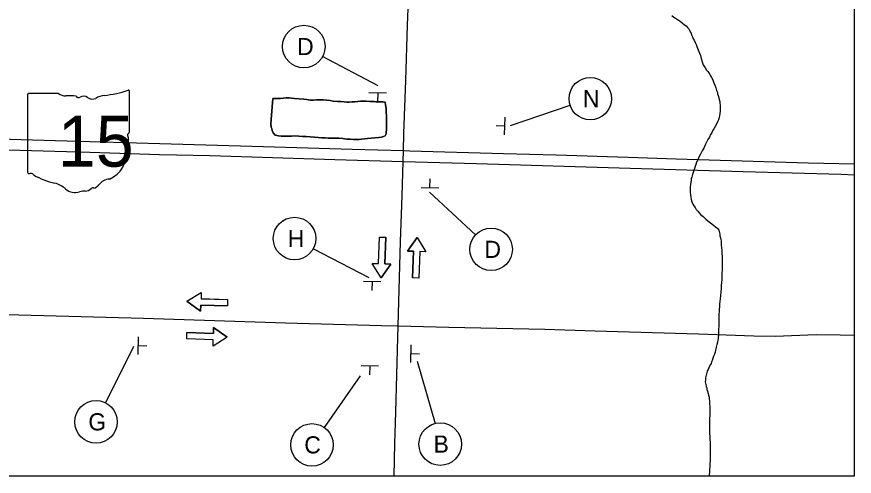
# Model space of a CAD drawing. Extents: x 1633.3 to 1707.6, y 1081.5 to 1106.
# Drawn here: x 1640.38 to 1648.01, y 1086.42 to 1090.6 of the extents above; entities that cross this region are included whole.
import ezdxf

# ---------------------------------------------------------------- set-up
doc = ezdxf.new("R2010")
doc.units = 0
for name, color, linetype in [('GM_X_County_Road', 7, 'Continuous'), ('GM_X_Minor_Lake', 7, 'Continuous'), ('GM_X_Minor_River', 7, 'Continuous'), ('GM_X_State_Route', 7, 'Continuous'), ('GM_X_State_Shield', 7, 'Continuous'), ('SH_Data', 7, 'Continuous'), ('SH_Text', 7, 'Continuous'), ('SN_P_Signs', 7, 'Continuous')]:
    doc.layers.add(name, color=color, linetype=linetype)

msp = doc.modelspace()

# ---------------------------------------------------------------- linework, layer by layer
at = {"layer": 'GM_X_County_Road'}
for points in [[(1643.9071, 1089.384), (1643.9114, 1089.5404), (1643.9273, 1090.0213), (1643.9445, 1090.5242), (1643.9565, 1090.8293), (1643.9741, 1091.2019), (1643.9856, 1091.5297), (1644.0086, 1092.1887), (1644.0208, 1092.5134), (1644.0277, 1092.6341), (1644.0323, 1092.6918), (1644.0369, 1092.7305), (1644.045, 1092.7687), (1644.0543, 1092.7889), (1644.0682, 1092.8156), (1644.0814, 1092.8346), (1644.102, 1092.8585)], [(1643.9044, 1089.2854), (1643.9071, 1089.384)], [(1643.8593, 1087.7897), (1643.881, 1088.5565), (1643.8957, 1088.9718), (1643.9044, 1089.2854)], [(1636.7029, 1087.9843), (1636.7291, 1087.9834), (1637.1782, 1087.9683), (1637.6688, 1087.9589), (1639.2, 1087.9178), (1640.4033, 1087.8897), (1641.5407, 1087.8579), (1642.8312, 1087.8177), (1643.7062, 1087.7937), (1643.8593, 1087.7897)], [(1643.8209, 1086.4207), (1643.8292, 1086.7195), (1643.8384, 1087.0037), (1643.8561, 1087.6817), (1643.8593, 1087.7897)], [(1643.8593, 1087.7897), (1644.3187, 1087.7778), (1645.1936, 1087.7586), (1645.6529, 1087.7435), (1646.5935, 1087.718), (1647.0963, 1087.6977), (1647.2932, 1087.6953), (1647.665, 1087.7091), (1647.8837, 1087.7067), (1648.0121, 1087.703)]]:
    msp.add_lwpolyline(points, dxfattribs=at)
at = {"layer": 'GM_X_Minor_Lake'}
for points in [[(1642.7169, 1089.8567), (1642.7222, 1089.8567), (1642.7329, 1089.8566), (1642.7463, 1089.8593), (1642.765, 1089.8565), (1642.7864, 1089.8591), (1642.8132, 1089.8617), (1642.84, 1089.8643), (1642.8667, 1089.8642), (1642.8881, 1089.8615), (1642.9149, 1089.8587), (1643.0005, 1089.8504), (1643.0272, 1089.8477), (1643.0567, 1089.8422), (1643.0861, 1089.8421), (1643.1155, 1089.8447), (1643.1476, 1089.8446), (1643.1771, 1089.8445), (1643.2065, 1089.8417), (1643.2386, 1089.839), (1643.268, 1089.8335), (1643.3082, 1089.8307), (1643.3376, 1089.8306), (1643.367, 1089.8279), (1643.3911, 1089.8251), (1643.4125, 1089.825), (1643.4393, 1089.8276), (1643.4634, 1089.8275), (1643.4901, 1089.8301), (1643.5142, 1089.8327), (1643.5383, 1089.8327), (1643.5677, 1089.8326), (1643.5998, 1089.8298), (1643.6212, 1089.8297), (1643.64, 1089.8297), (1643.656, 1089.8269), (1643.672, 1089.8269), (1643.6908, 1089.8268), (1643.7095, 1089.8268), (1643.7229, 1089.8267), (1643.7389, 1089.824), (1643.7442, 1089.7999), (1643.7469, 1089.7865), (1643.7495, 1089.7705), (1643.7495, 1089.749), (1643.7494, 1089.7276), (1643.752, 1089.7035), (1643.752, 1089.6875), (1643.752, 1089.6688), (1643.7519, 1089.6527), (1643.7519, 1089.634), (1643.7518, 1089.6179), (1643.7518, 1089.5725), (1643.749, 1089.5511), (1643.749, 1089.5377), (1643.7409, 1089.519), (1643.7248, 1089.511), (1643.7061, 1089.5057), (1643.682, 1089.5031), (1643.6419, 1089.5006), (1643.6124, 1089.498), (1643.5803, 1089.4927), (1643.5509, 1089.4902), (1643.5241, 1089.4876), (1643.5027, 1089.485), (1643.4786, 1089.485), (1643.4519, 1089.4851), (1643.4224, 1089.4879), (1643.3903, 1089.488), (1643.3556, 1089.4935), (1643.3208, 1089.4962), (1643.278, 1089.4964), (1643.2485, 1089.4965), (1643.2218, 1089.4966), (1643.1923, 1089.4993), (1643.1629, 1089.4994), (1643.1308, 1089.5022), (1643.096, 1089.505), (1643.0586, 1089.5078), (1643.0211, 1089.5133), (1642.9863, 1089.5134), (1642.9542, 1089.5161), (1642.9168, 1089.5189), (1642.8874, 1089.5164), (1642.8606, 1089.5138), (1642.8418, 1089.5138), (1642.8231, 1089.5139), (1642.8071, 1089.5139), (1642.7937, 1089.514), (1642.7696, 1089.5167), (1642.7375, 1089.5249), (1642.7188, 1089.5463), (1642.7109, 1089.5677), (1642.7082, 1089.5838), (1642.7029, 1089.5972), (1642.7003, 1089.624), (1642.7004, 1089.6668), (1642.7169, 1089.8567)], [(1642.7169, 1089.8567), (1642.7004, 1089.6668), (1642.7003, 1089.624), (1642.7029, 1089.5972), (1642.7082, 1089.5838), (1642.7109, 1089.5677), (1642.7188, 1089.5463), (1642.7375, 1089.5249), (1642.7696, 1089.5167), (1642.7937, 1089.514), (1642.8071, 1089.5139), (1642.8231, 1089.5139), (1642.8418, 1089.5138), (1642.8606, 1089.5138), (1642.8874, 1089.5164), (1642.9168, 1089.5189), (1642.9542, 1089.5161), (1642.9863, 1089.5134), (1643.0211, 1089.5133), (1643.0586, 1089.5078), (1643.096, 1089.505), (1643.1308, 1089.5022), (1643.1629, 1089.4994), (1643.1923, 1089.4993), (1643.2218, 1089.4966), (1643.2485, 1089.4965), (1643.278, 1089.4964), (1643.3208, 1089.4962), (1643.3556, 1089.4935), (1643.3903, 1089.488), (1643.4224, 1089.4879), (1643.4519, 1089.4851), (1643.4786, 1089.485), (1643.5027, 1089.485), (1643.5241, 1089.4876), (1643.5509, 1089.4902), (1643.5803, 1089.4927), (1643.6124, 1089.498), (1643.6419, 1089.5006), (1643.682, 1089.5031), (1643.7061, 1089.5057), (1643.7248, 1089.511), (1643.7409, 1089.519), (1643.749, 1089.5377), (1643.749, 1089.5511), (1643.7518, 1089.5725), (1643.7518, 1089.6179), (1643.7519, 1089.634), (1643.7519, 1089.6527), (1643.752, 1089.6688)], [(1643.752, 1089.6688), (1643.752, 1089.6875), (1643.752, 1089.7035), (1643.7494, 1089.7276), (1643.7495, 1089.749), (1643.7495, 1089.7705), (1643.7469, 1089.7865), (1643.7442, 1089.7999), (1643.7389, 1089.824), (1643.7229, 1089.8267), (1643.7095, 1089.8268), (1643.6908, 1089.8268), (1643.672, 1089.8269), (1643.656, 1089.8269), (1643.64, 1089.8297), (1643.6212, 1089.8297), (1643.5998, 1089.8298), (1643.5677, 1089.8326), (1643.5383, 1089.8327), (1643.5142, 1089.8327), (1643.4901, 1089.8301), (1643.4634, 1089.8275), (1643.4393, 1089.8276), (1643.4125, 1089.825), (1643.3911, 1089.8251), (1643.367, 1089.8279), (1643.3376, 1089.8306), (1643.3082, 1089.8307), (1643.268, 1089.8335), (1643.2386, 1089.839), (1643.2065, 1089.8417), (1643.1771, 1089.8445), (1643.1476, 1089.8446), (1643.1155, 1089.8447), (1643.0861, 1089.8421), (1643.0567, 1089.8422), (1643.0272, 1089.8477), (1643.0005, 1089.8504), (1642.9149, 1089.8587), (1642.8881, 1089.8615), (1642.8667, 1089.8642), (1642.84, 1089.8643), (1642.8132, 1089.8617), (1642.7864, 1089.8591), (1642.765, 1089.8565), (1642.7463, 1089.8593), (1642.7329, 1089.8566), (1642.7222, 1089.8567), (1642.7169, 1089.8567)]]:
    msp.add_lwpolyline(points, dxfattribs=at)
at = {"layer": 'GM_X_Minor_River'}
for points in [[(1646.3496, 1090.6129), (1646.3683, 1090.5995), (1646.3844, 1090.5887), (1646.4031, 1090.578), (1646.4271, 1090.5619), (1646.4458, 1090.5457), (1646.4672, 1090.5296), (1646.4805, 1090.5189), (1646.4939, 1090.5054), (1646.5046, 1090.492), (1646.5126, 1090.4786), (1646.5179, 1090.4652), (1646.5259, 1090.4518), (1646.5312, 1090.4384), (1646.5392, 1090.4197)], [(1646.5392, 1090.4197), (1646.5445, 1090.4009), (1646.5552, 1090.3875), (1646.5631, 1090.3688), (1646.5711, 1090.35), (1646.5791, 1090.3313), (1646.603, 1090.2697), (1646.611, 1090.2482), (1646.619, 1090.2214), (1646.627, 1090.192), (1646.6376, 1090.1652), (1646.6536, 1090.1357), (1646.6669, 1090.1169), (1646.6776, 1090.1035), (1646.6883, 1090.0901), (1646.6963, 1090.0767), (1646.7043, 1090.0633), (1646.7123, 1090.0499), (1646.7229, 1090.0285), (1646.7309, 1090.007), (1646.7415, 1089.9803), (1646.7522, 1089.9561), (1646.7575, 1089.9321), (1646.7654, 1089.9133), (1646.7681, 1089.8999), (1646.7734, 1089.8838), (1646.7787, 1089.8651), (1646.7814, 1089.849), (1646.7867, 1089.8303), (1646.7893, 1089.8142), (1646.7919, 1089.7982), (1646.7919, 1089.7821), (1646.7919, 1089.7607), (1646.7918, 1089.7447), (1646.7891, 1089.7179), (1646.7864, 1089.7045), (1646.781, 1089.6858), (1646.7756, 1089.6644), (1646.7675, 1089.6457), (1646.7568, 1089.6244), (1646.746, 1089.603), (1646.7326, 1089.5816), (1646.7218, 1089.5629), (1646.7138, 1089.5443), (1646.703, 1089.5309), (1646.695, 1089.5069), (1646.6788, 1089.4855), (1646.6681, 1089.4668), (1646.6573, 1089.4427), (1646.6439, 1089.4107), (1646.6278, 1089.3813), (1646.6116, 1089.3519), (1646.5982, 1089.3252), (1646.5874, 1089.3012), (1646.5767, 1089.2798), (1646.5686, 1089.2584), (1646.5444, 1089.1836), (1646.539, 1089.1649), (1646.5336, 1089.1435), (1646.5282, 1089.1275), (1646.5255, 1089.1114), (1646.5228, 1089.0954), (1646.52, 1089.074), (1646.5173, 1089.0499), (1646.5172, 1089.0285), (1646.5172, 1089.0044), (1646.5198, 1088.9803), (1646.5224, 1088.9563), (1646.5277, 1088.9375), (1646.533, 1088.9188), (1646.541, 1088.8973), (1646.5517, 1088.8812), (1646.5624, 1088.8652), (1646.573, 1088.8491), (1646.5864, 1088.833), (1646.5997, 1088.8169), (1646.6157, 1088.8008), (1646.6371, 1088.7847), (1646.6611, 1088.7605), (1646.6798, 1088.7444), (1646.7038, 1088.7256), (1646.7306, 1088.7041), (1646.7519, 1088.688), (1646.7653, 1088.6772), (1646.7786, 1088.6585), (1646.7839, 1088.637), (1646.7866, 1088.6237), (1646.7892, 1088.6076), (1646.7945, 1088.5888), (1646.7972, 1088.5755), (1646.7998, 1088.5621), (1646.7998, 1088.5433), (1646.7997, 1088.5246), (1646.8023, 1088.5005), (1646.805, 1088.4738), (1646.8076, 1088.4497), (1646.8102, 1088.4176), (1646.8101, 1088.3962), (1646.8101, 1088.3694), (1646.81, 1088.3453), (1646.8099, 1088.3159)], [(1646.8099, 1088.3159), (1646.8071, 1088.249), (1646.8071, 1088.2303), (1646.807, 1088.2089), (1646.8043, 1088.1848), (1646.8015, 1088.1554), (1646.7988, 1088.1286), (1646.796, 1088.0965), (1646.7933, 1088.0645), (1646.7906, 1088.035), (1646.7878, 1088.011), (1646.7851, 1087.9869), (1646.785, 1087.9628), (1646.7823, 1087.9414), (1646.7823, 1087.9173), (1646.7795, 1087.8986), (1646.7795, 1087.8745), (1646.7794, 1087.8398), (1646.7793, 1087.8103), (1646.7793, 1087.7836), (1646.7766, 1087.7595), (1646.7765, 1087.7381), (1646.7765, 1087.7167), (1646.7764, 1087.7006), (1646.7737, 1087.6873), (1646.7737, 1087.6739), (1646.7683, 1087.6579), (1646.7656, 1087.6418), (1646.7602, 1087.6204), (1646.7548, 1087.5964), (1646.7521, 1087.5803), (1646.7494, 1087.567), (1646.744, 1087.5482), (1646.7386, 1087.5322), (1646.7332, 1087.5189), (1646.7278, 1087.5055), (1646.7197, 1087.4841), (1646.7116, 1087.4601), (1646.7089, 1087.4467), (1646.6982, 1087.428), (1646.6874, 1087.4066), (1646.6821, 1087.3933), (1646.674, 1087.3772), (1646.6578, 1087.3158), (1646.6578, 1087.297), (1646.655, 1087.2783), (1646.6603, 1087.2542), (1646.663, 1087.2381), (1646.6683, 1087.2248), (1646.6709, 1087.2087), (1646.6763, 1087.1953), (1646.6816, 1087.1739), (1646.6842, 1087.1578), (1646.6895, 1087.1417), (1646.6922, 1087.1284), (1646.6948, 1087.1043), (1646.6947, 1087.0909), (1646.6947, 1087.0775), (1646.6973, 1087.0588), (1646.6973, 1087.0347), (1646.6972, 1086.9812), (1646.6944, 1086.9384), (1646.6943, 1086.9036), (1646.6942, 1086.8688), (1646.6942, 1086.8367), (1646.6941, 1086.81), (1646.6967, 1086.7832), (1646.6966, 1086.7538), (1646.6992, 1086.727), (1646.6992, 1086.6922), (1646.6991, 1086.6655), (1646.699, 1086.6307), (1646.699, 1086.5986), (1646.6989, 1086.5638), (1646.6961, 1086.5344), (1646.6961, 1086.5103), (1646.6934, 1086.4863), (1646.6933, 1086.4595), (1646.6906, 1086.4327), (1646.6894, 1086.4207)]]:
    msp.add_lwpolyline(points, dxfattribs=at)
at = {"layer": 'GM_X_State_Route'}
for points in [[(1633.3121, 1089.6917), (1633.8444, 1089.6764), (1634.5421, 1089.656), (1635.0244, 1089.6397), (1635.5067, 1089.6277), (1636.4013, 1089.603), (1636.7895, 1089.5915), (1637.6692, 1089.5652), (1639.746, 1089.5046), (1640.4237, 1089.486), (1640.9483, 1089.4695), (1641.5823, 1089.4514), (1642.6316, 1089.4208), (1643.4405, 1089.3971), (1643.9071, 1089.384), (1643.9651, 1089.3826), (1644.8177, 1089.3571), (1645.2987, 1089.3441), (1645.9544, 1089.3239), (1646.3915, 1089.3102), (1647.5918, 1089.2715), (1647.7355, 1089.2693), (1648.0121, 1089.264)], [(1633.3121, 1089.5922), (1634.2415, 1089.565), (1635.2906, 1089.5338), (1635.99, 1089.5137), (1636.7846, 1089.489), (1637.3802, 1089.4708), (1637.8182, 1089.4595), (1638.6457, 1089.4389), (1639.4549, 1089.4149), (1641.0515, 1089.3682), (1641.6858, 1089.3496), (1642.145, 1089.338), (1643.2823, 1089.3034), (1643.9044, 1089.2854), (1644.5726, 1089.2656), (1645.9723, 1089.2243), (1647.0002, 1089.1934), (1647.8935, 1089.1689), (1648.0121, 1089.1646)]]:
    msp.add_lwpolyline(points, dxfattribs=at)
at = {"layer": 'GM_X_State_Shield'}
for p, q in [((1641.4116, 1089.5533), (1641.4116, 1089.9218)), ((1640.4835, 1089.8923), (1640.4835, 1089.1878)), ((1640.7644, 1089.9044), (1640.4926, 1089.9044)), ((1641.4115, 1089.5534), (1641.4116, 1089.5533))]:
    msp.add_line(p, q, dxfattribs=at)
for centre, radius, start, end in [((1641.081, 1090.8647), 0.9842, 275.84447, 288.90645), ((1641.4013, 1089.9234), 0.0103, 351.86209, 97.738), ((1640.4941, 1089.8938), 0.0108, 98.1301, 188.1301), ((1640.8292, 1089.9861), 0.1043, 231.61951, 271.11188), ((1640.8638, 1089.5089), 0.3744, 80.48669, 94.98827), ((1640.9487, 1089.8974), 0.0301, 219.79206, 297.10237), ((1640.9929, 1089.816), 0.0626, 54.46668, 119.14113), ((1641.0737, 1089.9277), 0.0753, 233.85621, 294.82819), ((1641.2066, 1089.6892), 0.198, 97.34618, 120.76885), ((1641.4092, 1089.5263), 0.016, 107.94398, 210.33697), ((1641.4006, 1089.5519), 0.0111, 289.60381, 7.73413), ((1641.3075, 1089.4797), 0.096, 340.03296, 23.64957), ((1641.1361, 1089.3523), 0.2462, 292.30889, 8.98584), ((1641.4486, 1089.3991), 0.0698, 136.8065, 186.92959), ((1640.4942, 1089.1863), 0.0108, 171.95839, 258.30661), ((1640.4959, 1089.2584), 0.0828, 267.33899, 280.60386), ((1640.5128, 1089.1472), 0.0298, 29.74838, 93.27175), ((1640.8897, 1089.7801), 0.7108, 240.41292, 257.1985), ((1640.6778, 1088.8714), 0.2224, 47.18416, 75.83597), ((1641.2399, 1088.9901), 0.1348, 94.40312, 142.57675), ((1640.9183, 1089.1437), 0.1411, 230.70037, 286.29184), ((1640.9998, 1088.9001), 0.116, 85.69512, 111.20995), ((1641.0101, 1089.0909), 0.0752, 268.77702, 315.54927), ((1641.0781, 1089.0227), 0.0212, 65.75173, 132.64842), ((1641.0691, 1089.1196), 0.0795, 282.87319, 323.27711)]:
    msp.add_arc(centre, radius, start, end, dxfattribs=at)
at = {"layer": 'SH_Data'}
msp.add_lwpolyline([(1633.3121, 1106.0207), (1648.0121, 1106.0207), (1648.0121, 1086.4207), (1633.3121, 1086.4207)], close=True, dxfattribs=at)
at = {"layer": 'SH_Text'}
for p, q in [((1643.6771, 1089.9731), (1643.1697, 1090.2389)), ((1644.8814, 1089.6128), (1645.4241, 1089.7963)), ((1644.1428, 1089.0064), (1644.5641, 1088.6182)), ((1643.6801, 1088.3555), (1643.6886, 1088.5974)), ((1643.6886, 1088.5974), (1643.7465, 1088.5954)), ((1643.7381, 1088.3535), (1643.7465, 1088.5954)), ((1644.0316, 1088.594), (1643.9424, 1088.4696)), ((1644.0316, 1088.594), (1644.1119, 1088.4637)), ((1643.5931, 1088.2255), (1643.0857, 1088.4913)), ((1643.9424, 1088.4696), (1643.997, 1088.4677)), ((1643.997, 1088.4677), (1643.9886, 1088.2258)), ((1644.055, 1088.4656), (1644.0465, 1088.2238)), ((1644.1119, 1088.4637), (1644.055, 1088.4656)), ((1643.7035, 1088.2271), (1643.6232, 1088.3575)), ((1643.6232, 1088.3575), (1643.6801, 1088.3555)), ((1643.7035, 1088.2271), (1643.7927, 1088.3516)), ((1643.7927, 1088.3516), (1643.7381, 1088.3535)), ((1644.0465, 1088.2238), (1643.9886, 1088.2258)), ((1641.9352, 1088.0129), (1642.0655, 1088.0934)), ((1642.0655, 1088.0934), (1642.0636, 1088.0365)), ((1641.9352, 1088.0129), (1642.0598, 1087.9239)), ((1642.0636, 1088.0365), (1642.3055, 1088.0284)), ((1642.3055, 1088.0284), (1642.3035, 1087.9704)), ((1642.0598, 1087.9239), (1642.0616, 1087.9785)), ((1642.0616, 1087.9785), (1642.3035, 1087.9704)), ((1641.9324, 1087.6699), (1641.9343, 1087.7278)), ((1642.1762, 1087.7198), (1641.9343, 1087.7278)), ((1642.178, 1087.7743), (1642.1762, 1087.7198)), ((1642.3026, 1087.6854), (1642.178, 1087.7743)), ((1642.1743, 1087.6618), (1641.9324, 1087.6699)), ((1642.3026, 1087.6854), (1642.1724, 1087.6048)), ((1642.1724, 1087.6048), (1642.1743, 1087.6618)), ((1641.4476, 1087.6024), (1641.1944, 1087.0885)), ((1644.0309, 1087.4684), (1644.194, 1086.9008)), ((1643.5128, 1087.3343), (1643.1859, 1086.8639))]:
    msp.add_line(p, q, dxfattribs=at)
for points in [[(1643.9071, 1089.384), (1643.9114, 1089.5404), (1643.9273, 1090.0213), (1643.9445, 1090.5242), (1643.9565, 1090.8293), (1643.9741, 1091.2019), (1643.9856, 1091.5297), (1644.0086, 1092.1887), (1644.0208, 1092.5134), (1644.0277, 1092.6341), (1644.0323, 1092.6918), (1644.0369, 1092.7305), (1644.045, 1092.7687), (1644.0543, 1092.7889), (1644.0682, 1092.8156), (1644.0814, 1092.8346), (1644.102, 1092.8585)], [(1643.8593, 1087.7897), (1643.881, 1088.5565), (1643.8957, 1088.9718), (1643.9071, 1089.384)], [(1636.7029, 1087.9843), (1636.7291, 1087.9834), (1637.1782, 1087.9683), (1637.6688, 1087.9589), (1639.2, 1087.9178), (1640.4033, 1087.8897), (1641.5407, 1087.8579), (1642.8312, 1087.8177), (1643.7062, 1087.7937), (1643.8593, 1087.7897)]]:
    msp.add_lwpolyline(points, dxfattribs=at)
for points in [[(1643.7465, 1088.5954), (1643.7381, 1088.3535), (1643.7927, 1088.3516), (1643.7035, 1088.2271), (1643.6232, 1088.3575), (1643.6802, 1088.3555), (1643.6886, 1088.5974)], [(1643.9886, 1088.2258), (1643.997, 1088.4677), (1643.9424, 1088.4696), (1644.0316, 1088.594), (1644.1119, 1088.4637), (1644.055, 1088.4656), (1644.0465, 1088.2238)], [(1642.3035, 1087.9704), (1642.0616, 1087.9785), (1642.0598, 1087.9239), (1641.9352, 1088.0129), (1642.0654, 1088.0934), (1642.0636, 1088.0364), (1642.3055, 1088.0284)], [(1641.9343, 1087.7278), (1642.1762, 1087.7198), (1642.178, 1087.7743), (1642.3027, 1087.6854), (1642.1724, 1087.6048), (1642.1743, 1087.6618), (1641.9324, 1087.6699)]]:
    msp.add_lwpolyline(points, close=True, dxfattribs=at)
for centre in [(1642.9992, 1090.3307), (1645.6082, 1089.8562), (1642.9152, 1088.5832), (1644.705, 1088.4853), (1641.1068, 1086.9158), (1643.0735, 1086.7062), (1644.2416, 1086.7131)]:
    msp.add_circle(centre, 0.1936, dxfattribs=at)
at = {"layer": 'SN_P_Signs'}
for p, q in [((1643.7527, 1089.9059), (1643.5928, 1089.9101)), ((1643.6727, 1089.908), (1643.6707, 1089.8281)), ((1644.8274, 1089.5269), (1644.8321, 1089.6868)), ((1644.8298, 1089.6069), (1644.7498, 1089.6092)), ((1644.1479, 1089.0466), (1644.1499, 1089.1266)), ((1644.0679, 1089.0487), (1644.2278, 1089.0445)), ((1643.7014, 1088.1898), (1643.5414, 1088.1939)), ((1643.6214, 1088.1918), (1643.6193, 1088.1119)), ((1641.4913, 1087.6892), (1641.4865, 1087.5293)), ((1641.4889, 1087.6093), (1641.5689, 1087.6069)), ((1643.9744, 1087.6167), (1643.9696, 1087.4568)), ((1643.972, 1087.5367), (1644.052, 1087.5343)), ((1643.6808, 1087.4212), (1643.5208, 1087.4254)), ((1643.6008, 1087.4233), (1643.5987, 1087.3434))]:
    msp.add_line(p, q, dxfattribs=at)

# ---------------------------------------------------------------- texts
at = {"layer": 'GM_X_State_Shield'}
msp.add_text('15', height=0.46406, dxfattribs=at).set_placement((1640.7598, 1089.2375))
at = {"layer": 'SH_Text'}
for s, p in [('D', (1642.9384, 1090.2527)), ('N', (1645.5413, 1089.7782)), ('H', (1642.8519, 1088.5052)), ('D', (1644.6442, 1088.4073)), ('G', (1641.0368, 1086.8378)), ('B', (1644.1808, 1086.6351)), ('C', (1643.0035, 1086.6282))]:
    msp.add_text(s, height=0.156, dxfattribs=at).set_placement(p)

doc.saveas('drawing.dxf')
